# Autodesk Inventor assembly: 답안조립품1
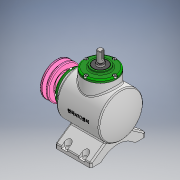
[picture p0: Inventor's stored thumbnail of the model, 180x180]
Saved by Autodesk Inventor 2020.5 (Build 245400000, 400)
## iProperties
Created: 2023-12
Part Number: 답안조립품1
Document SubType Name: Weldment
Designer: 1강의실14
Weld Material: Welded Aluminum-6061
Author: 1강의실14
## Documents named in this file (17)
- C:\Users\1강의실14\Desktop\731203V1001\답안조립품1.iam
- C:\Users\1강의실14\Desktop\731203V1001\본체.ipt
- C:\Users\1강의실14\Desktop\731203V1001\커버.ipt
- C:\Users\1강의실14\Desktop\731203V1001\베어링 6203.ipt
- C:\Users\1강의실14\Desktop\731203V1001\오일실 17 x 32 x 8.ipt
- C:\Users\1강의실14\Desktop\731203V1001\메인 축.ipt
- 메인 축.ipt
- C:\Users\1강의실14\Desktop\731203V1001\키 5 x 5 x 14.ipt
- C:\Users\1강의실14\Desktop\731203V1001\메인 베벨기어.ipt
- C:\Users\1강의실14\Desktop\731203V1001\서브 축.ipt
- 서브 축.ipt
- C:\Users\1강의실14\Desktop\731203V1001\키 4 x 4 x 14.ipt
- C:\Users\1강의실14\Desktop\731203V1001\서브 베벨기어.ipt
- C:\Users\1강의실14\Desktop\731203V1001\V-벨트풀리.ipt
- C:\Users\1강의실14\Desktop\731203V1001\볼트 M4 x 10.ipt
- C:\Users\1강의실14\Desktop\731203V1001\와셔 4 x 16.ipt
- C:\Users\1강의실14\Desktop\731203V1001\육각볼트 M4 x 8.ipt
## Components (1 placed, 1 different names)
1. V-벨트풀리:1
